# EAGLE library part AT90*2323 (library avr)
MICROCONTROLLER 2 Kbytes FLASH 128 bytes SRAM 128 bytes EEPROM
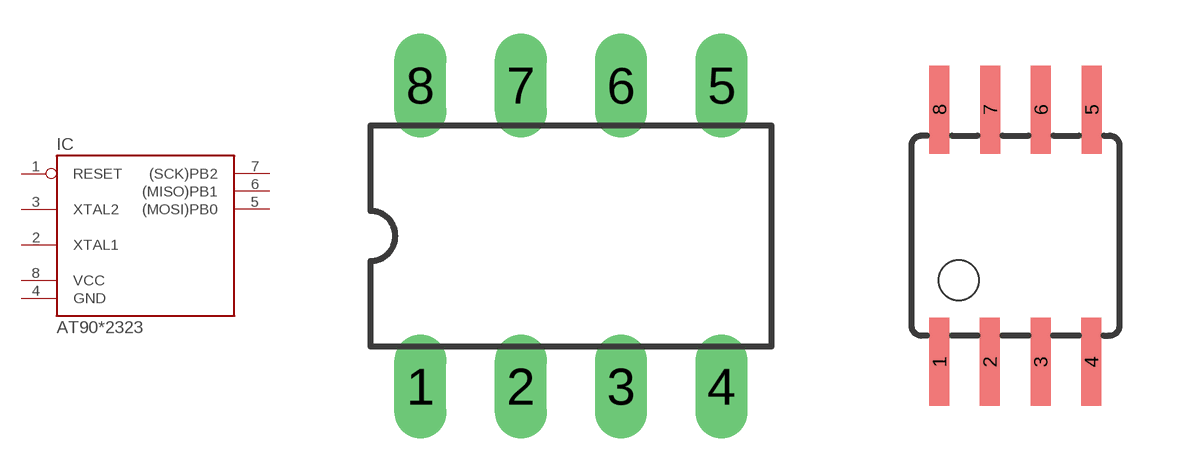
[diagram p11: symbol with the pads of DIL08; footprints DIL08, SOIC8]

Designator prefix IC

## AT90LS2323P, AT90S2323P  [DIL08]
1  RESET  in
2  XTAL1
3  XTAL2
4  GND  pwr
5  (MOSI)PB0
6  (MISO)PB1
7  (SCK)PB2
8  VCC  pwr

## AT90LS2323S, AT90S2323S  [SOIC8]
Pads as for DIL08

## Footprint DIL08 (pad centres in mm)
Dual In Line
drill 0.813 long: 1 -3.81,-3.81; 2 -1.27,-3.81; 3 1.27,-3.81; 4 3.81,-3.81; 5 3.81,3.81; 6 1.27,3.81; 7 -1.27,3.81; 8 -3.81,3.81

## Footprint SOIC8 (pad centres in mm)
Wide Plastic Gull Wing Small Outline Package
smd 0.5 x 2.2: 1 -1.905,-3.154; 2 -0.645,-3.154; 3 0.625,-3.154; 4 1.895,-3.154; 5 1.905,3.154; 6 0.635,3.154; 7 -0.635,3.154; 8 -1.905,3.154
